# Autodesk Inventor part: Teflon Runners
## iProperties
Shininess: 64.0
Length Units: 11272
Angle Units: 11279
Time Units: 11290
Mass Units: 11286
Length Display Precision: 3
Angle Display Precision: 2
Compacted: True
Part Number: Teflon Runners
Document SubType Name: Modeling
Created: 2003-10
Designer: jpittman
Manufacturer: Standard
Standards Organization: Custom
Density: 0.0
Volumn: 0.0
Area: 0.0
PropertySet Name: Model Information
Control State: 0
Master: False
Checked Out: False
Author: jpittman
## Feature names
1. Extrusion1
2. Hole1
